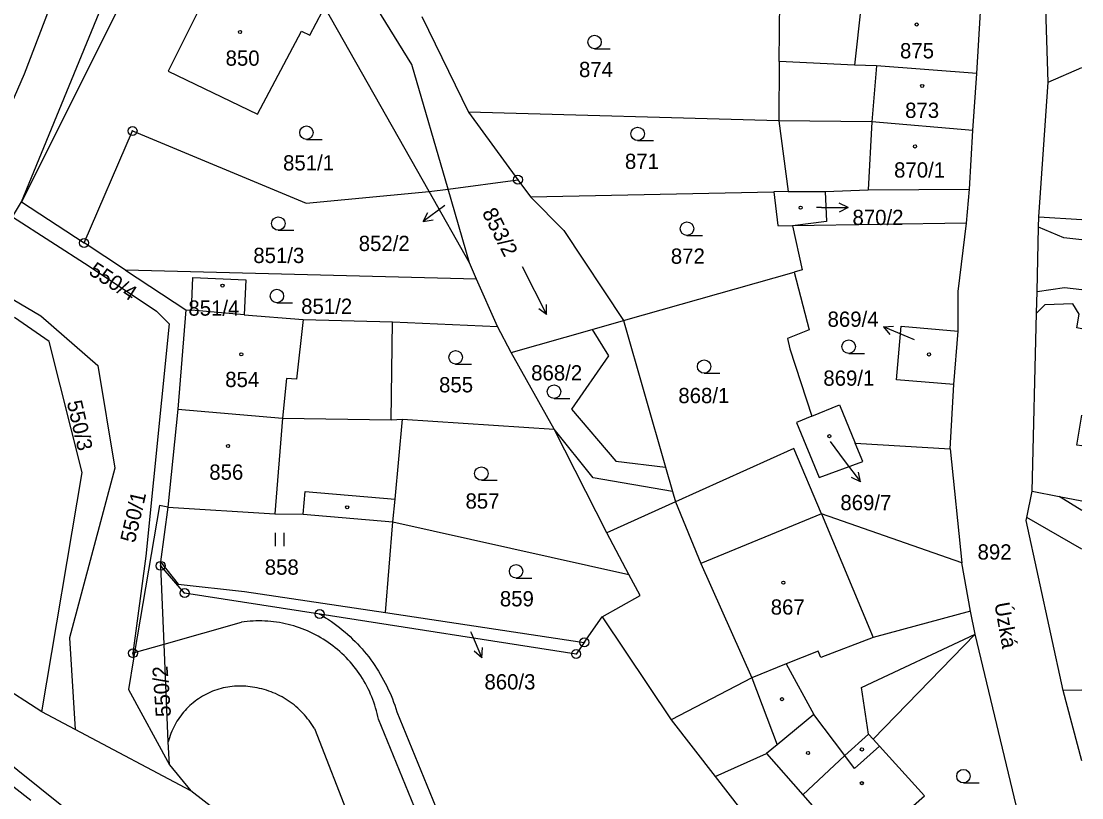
# Model space of a CAD drawing. Extents: x -776606 to -776076, y -974328 to -973875.
# Drawn here: x -776193.8 to -776075.5, y -974133.7 to -974047.1 of the extents above; entities that cross this region are included whole.
import ezdxf

# ---------------------------------------------------------------- set-up
doc = ezdxf.new("R2010")
doc.units = 0
for name, color, linetype in [('Hranice parcel', 7, 'Continuous'), ('Parcelní čísla', 7, 'Continuous'), ('Pop  PČ popisy', 7, 'Continuous'), ('Poz předměty', 7, 'Continuous'), ('Vnitřní kresba', 7, 'Continuous'), ('Značky bodu BP', 7, 'Continuous'), ('Značky budov', 7, 'Continuous'), ('Značky kultur', 7, 'Continuous')]:
    doc.layers.add(name, color=color, linetype=linetype)

msp = doc.modelspace()

# ---------------------------------------------------------------- linework, layer by layer
at = {"layer": 'Hranice parcel'}
for p, q in [((-776172.13, -974024.06), (-776193.76, -974067.27)), ((-776148.31, -974066.12), (-776172.13, -974024.06)), ((-776109.25, -974051.62), (-776109.18, -974044.78)), ((-776087.23, -974052.97), (-776086.8, -974046.07)), ((-776149.12, -974046.61), (-776143.9, -974057.28)), ((-776109.25, -974051.62), (-776109.32, -974058.22)), ((-776079.28, -974053.91), (-776075.52, -974052.27)), ((-776087.67, -974059.31), (-776087.23, -974052.97)), ((-776080.3, -974068.92), (-776079.28, -974053.91)), ((-776109.32, -974058.22), (-776143.9, -974057.28)), ((-776143.9, -974057.28), (-776138.41, -974064.8)), ((-776109.32, -974058.22), (-776108.28, -974066.12)), ((-776146.2, -974065.84), (-776138.41, -974064.8)), ((-776138.41, -974064.8), (-776137.02, -974066.7)), ((-776148.31, -974066.12), (-776146.2, -974065.84)), ((-776143.81, -974074.06), (-776148.31, -974066.12)), ((-776143.81, -974074.06), (-776146.2, -974065.84)), ((-776137.02, -974066.7), (-776109.88, -974066.15)), ((-776108.28, -974066.12), (-776109.88, -974066.15)), ((-776194.77, -974068.92), (-776193.76, -974067.27)), ((-776193.76, -974067.27), (-776186.79, -974071.85)), ((-776194.77, -974068.92), (-776186.22, -974074.45)), ((-776080.33, -974070.1), (-776080.3, -974068.92)), ((-776080.3, -974068.92), (-776075.52, -974069.23)), ((-776088.36, -974069.64), (-776107.78, -974069.96)), ((-776107.78, -974069.96), (-776106.71, -974074.86)), ((-776182.18, -974074.88), (-776186.79, -974071.85)), ((-776143.01, -974075.9), (-776182.18, -974074.88)), ((-776182.18, -974074.88), (-776175.43, -974079.31)), ((-776143.01, -974075.9), (-776143.81, -974074.06)), ((-776106.71, -974074.86), (-776107.61, -974075.12)), ((-776140.7, -974081.18), (-776143.01, -974075.9)), ((-776126.62, -974080.51), (-776107.61, -974075.12)), ((-776175.43, -974079.31), (-776176.35, -974090.4)), ((-776175.43, -974079.31), (-776174.82, -974079.36)), ((-776168.93, -974079.85), (-776174.82, -974079.36)), ((-776168.93, -974079.85), (-776162.35, -974080.4)), ((-776162.35, -974080.4), (-776152.38, -974080.66)), ((-776152.53, -974091.56), (-776152.38, -974080.66)), ((-776152.38, -974080.66), (-776140.7, -974081.18)), ((-776130.11, -974081.5), (-776126.62, -974080.51)), ((-776081.05, -974099.52), (-776080.56, -974079.68)), ((-776139.16, -974084.07), (-776140.7, -974081.18)), ((-776139.16, -974084.07), (-776130.11, -974081.5)), ((-776089.79, -974087.64), (-776089.3, -974081.68)), ((-776134.36, -974092.61), (-776139.16, -974084.07)), ((-776090.2, -974094.79), (-776089.79, -974087.64)), ((-776176.35, -974090.4), (-776177.45, -974101.31)), ((-776152.53, -974091.56), (-776151.27, -974091.49)), ((-776151.27, -974091.49), (-776134.36, -974092.61)), ((-776128.48, -974104.18), (-776134.36, -974092.61)), ((-776100.78, -974094.18), (-776090.2, -974094.79)), ((-776090.2, -974094.79), (-776088.89, -974107.52)), ((-776081.66, -974102.46), (-776081.05, -974099.52)), ((-776081.05, -974099.52), (-776078.04, -974100.11)), ((-776078.04, -974100.11), (-776075.52, -974100.6)), ((-776177.45, -974101.31), (-776178.27, -974107.4)), ((-776153.17, -974113.06), (-776152.34, -974102.95)), ((-776152.34, -974102.95), (-776126.03, -974108.8)), ((-776126.03, -974108.8), (-776128.48, -974104.18)), ((-776178.25, -974107.85), (-776178.27, -974107.4)), ((-776177.87, -974116.6), (-776178.25, -974107.85)), ((-776087.93, -974112.92), (-776088.89, -974107.52)), ((-776191.49, -974124.12), (-776209.73, -974112.42)), ((-776153.17, -974113.06), (-776131, -974116.38)), ((-776131, -974116.38), (-776129, -974113.52)), ((-776129, -974113.52), (-776121.33, -974125.02)), ((-776087.39, -974115.46), (-776087.93, -974112.92)), ((-776098.8, -974127.16), (-776087.39, -974115.46)), ((-776079.84, -974147.11), (-776087.39, -974115.46)), ((-776181.28, -974118.22), (-776181.85, -974121.62)), ((-776181.85, -974121.62), (-776177.26, -974130.04)), ((-776075.52, -974121.72), (-776077.59, -974121.76)), ((-776075.52, -974129.58), (-776077.59, -974121.76)), ((-776192.75, -974134.02), (-776207.36, -974122.58)), ((-776187.78, -974126.09), (-776191.49, -974124.12)), ((-776174.9, -974132.93), (-776187.78, -974126.09)), ((-776098.09, -974127.94), (-776098.8, -974127.16)), ((-776177.26, -974130.04), (-776174.9, -974132.93)), ((-776151.23, -974151.21), (-776174.9, -974132.93))]:
    msp.add_line(p, q, dxfattribs=at)
for points in [[(-776193.76, -974067.27), (-776174.47, -974020.28), (-776171.99, -974017.55)], [(-776146.2, -974065.84), (-776150.23, -974051.95), (-776169.88, -974020.23)], [(-776079.28, -974053.91), (-776079.58, -974044.52), (-776077.53, -974039.59), (-776075.52, -974034.53)], [(-776171.44, -974040.68), (-776177.4, -974052.7), (-776167.44, -974057.5), (-776162.53, -974048.25), (-776161.63, -974048.7), (-776160.2, -974046), (-776171.44, -974040.68)], [(-776087.23, -974052.97), (-776098.4, -974052.1), (-776100.85, -974052.03), (-776109.25, -974051.62)], [(-776087.67, -974059.31), (-776098.95, -974058.35), (-776109.32, -974058.22)], [(-776186.79, -974071.85), (-776181.39, -974059.36), (-776162.03, -974067.4), (-776148.31, -974066.12)], [(-776088.36, -974069.64), (-776088.04, -974065.84), (-776087.67, -974059.31)], [(-776109.88, -974066.15), (-776109.43, -974069.89), (-776107.78, -974069.96)], [(-776108.28, -974066.12), (-776104.12, -974066.1), (-776103.99, -974069.47), (-776107.78, -974069.96)], [(-776137.02, -974066.7), (-776133.27, -974070.47), (-776126.62, -974080.51)], [(-776089.3, -974081.68), (-776089.29, -974077.28), (-776088.36, -974069.64)], [(-776080.56, -974079.68), (-776080.51, -974077.28), (-776080.33, -974070.1)], [(-776075.52, -974071.52), (-776077.51, -974071.29), (-776080.33, -974070.1)], [(-776186.22, -974074.45), (-776178.73, -974079.45), (-776177.29, -974080.87), (-776179.9, -974106.76)], [(-776198.63, -974075.84), (-776191.6, -974079.99), (-776185.25, -974085.51), (-776183.37, -974096.97), (-776188.41, -974115.88), (-776187.78, -974126.09)], [(-776174.82, -974079.36), (-776174.65, -974075.7), (-776168.76, -974075.98), (-776168.93, -974079.85)], [(-776107.61, -974075.12), (-776105.93, -974081.53), (-776108.34, -974082.51), (-776108.07, -974083.66), (-776105.61, -974091.16)], [(-776075.52, -974081.42), (-776076.06, -974081.32), (-776075.81, -974079.8), (-776076.53, -974078.63), (-776079.63, -974078.74), (-776080.56, -974079.68)], [(-776191.49, -974124.12), (-776186.99, -974097.43), (-776190.67, -974082.84), (-776194.55, -974080.16)], [(-776130.11, -974081.5), (-776128.3, -974084.44), (-776132.44, -974090.38), (-776127.47, -974096.19), (-776121.94, -974096.86), (-776121.17, -974099.55), (-776130.03, -974098.04), (-776134.36, -974092.61)], [(-776089.79, -974087.64), (-776096.17, -974087.11), (-776095.67, -974081.13), (-776089.3, -974081.68)], [(-776105.61, -974091.16), (-776102.55, -974089.9), (-776100.78, -974094.18)], [(-776176.35, -974090.4), (-776164.65, -974091.4), (-776152.53, -974091.56)], [(-776152.34, -974102.95), (-776152.11, -974100.42), (-776151.27, -974091.49)], [(-776105.61, -974091.16), (-776107.32, -974091.87), (-776104.79, -974098.01), (-776099.94, -974096.23), (-776100.78, -974094.18)], [(-776075.52, -974094.47), (-776076.05, -974094.38), (-776075.52, -974091.06)], [(-776088.89, -974107.52), (-776104.54, -974102.04), (-776107.63, -974094.75), (-776120.83, -974100.72), (-776128.48, -974104.18)], [(-776075.52, -974101.67), (-776078.04, -974100.11)], [(-776177.45, -974101.31), (-776178.37, -974101.14), (-776181.16, -974117.53), (-776181.28, -974118.22)], [(-776177.45, -974101.31), (-776165.5, -974102.05), (-776162.34, -974102.1), (-776152.34, -974102.95)], [(-776077.59, -974121.76), (-776081.73, -974102.8), (-776081.66, -974102.46)], [(-776075.52, -974105.99), (-776081.66, -974102.46)], [(-776179.9, -974106.76), (-776181.35, -974117.59), (-776181.28, -974118.22)], [(-776178.27, -974107.4), (-776176.29, -974109.9), (-776168.89, -974110.71), (-776153.17, -974113.06)], [(-776131, -974116.38), (-776131.91, -974117.68), (-776160.51, -974113.23), (-776175.58, -974110.89), (-776178.25, -974107.85)], [(-776129, -974113.52), (-776124.77, -974111.17), (-776126.03, -974108.8)], [(-776087.93, -974112.92), (-776098.8, -974115.84), (-776104.62, -974118.06), (-776104.9, -974117.36), (-776108.49, -974118.79), (-776112.33, -974120.32), (-776121.33, -974125.02)], [(-776177.26, -974130.04), (-776177.4, -974127.49), (-776177.87, -974116.6)], [(-776121.33, -974125.02), (-776116.42, -974131.34), (-776106, -974144.74)], [(-776098.85, -974138.57), (-776093.06, -974133.49), (-776098.09, -974127.94)]]:
    msp.add_lwpolyline(points, dxfattribs=at)
at = {"layer": 'Pop  PČ popisy'}
for p, q in [((-776146.54, -974067.68), (-776148.97, -974069.44)), ((-776101.56, -974067.9), (-776102.56, -974067.4)), ((-776148.97, -974069.44), (-776148.45, -974068.45)), ((-776104.56, -974067.9), (-776105.12, -974067.9)), ((-776104.56, -974067.9), (-776101.56, -974067.9)), ((-776101.56, -974067.9), (-776102.56, -974068.4)), ((-776148.97, -974069.44), (-776147.86, -974069.26)), ((-776097.64, -974081.2), (-776096.53, -974081.13)), ((-776094.88, -974082.37), (-776097.64, -974081.2)), ((-776097.64, -974081.2), (-776096.92, -974082.05)), ((-776094.19, -974082.66), (-776094.88, -974082.37)), ((-776103.57, -974094), (-776102.01, -974096.09)), ((-776102.01, -974096.09), (-776100.2, -974098.49)), ((-776100.2, -974098.49), (-776100.41, -974097.39)), ((-776100.2, -974098.49), (-776101.21, -974097.99)), ((-776143.68, -974115.16), (-776143.61, -974115.33)), ((-776143.61, -974115.33), (-776142.44, -974118.09)), ((-776142.44, -974118.09), (-776143.29, -974117.37)), ((-776142.44, -974118.09), (-776142.37, -974116.97))]:
    msp.add_line(p, q, dxfattribs=at)
at = {"layer": 'Poz předměty'}
for p, q in [((-776188.57, -974040.14), (-776193.46, -974053.03)), ((-776193.46, -974053.03), (-776205.51, -974080.41))]:
    msp.add_line(p, q, dxfattribs=at)
at = {"layer": 'Vnitřní kresba'}
for p, q in [((-776100.12, -974045.3), (-776100.85, -974052.03)), ((-776098.4, -974052.1), (-776098.95, -974058.35)), ((-776098.95, -974058.35), (-776099.35, -974065.94)), ((-776104.12, -974066.1), (-776099.35, -974065.94)), ((-776099.35, -974065.94), (-776088.04, -974065.84)), ((-776080.51, -974077.28), (-776077.46, -974076.83)), ((-776077.46, -974076.83), (-776075.52, -974077.04)), ((-776162.35, -974080.4), (-776163.09, -974087.03)), ((-776126.62, -974080.51), (-776121.94, -974096.86)), ((-776164.21, -974086.98), (-776164.65, -974091.4)), ((-776163.09, -974087.03), (-776164.21, -974086.98)), ((-776164.65, -974091.4), (-776165.5, -974102.05)), ((-776162.34, -974102.1), (-776162.12, -974099.58)), ((-776162.12, -974099.58), (-776152.11, -974100.42)), ((-776121.17, -974099.55), (-776120.83, -974100.72)), ((-776120.83, -974100.72), (-776118, -974107.6)), ((-776104.54, -974102.04), (-776118, -974107.6)), ((-776104.54, -974102.04), (-776098.8, -974115.84)), ((-776118, -974107.6), (-776112.33, -974120.32)), ((-776177.87, -974116.6), (-776169.25, -974114.14)), ((-776100.08, -974121.41), (-776087.39, -974115.46)), ((-776181.16, -974117.53), (-776177.87, -974116.6)), ((-776181.16, -974117.53), (-776181.35, -974117.59)), ((-776108.49, -974118.79), (-776105.41, -974124.43)), ((-776112.33, -974120.32), (-776109.49, -974127.79)), ((-776099.3, -974126.61), (-776100.08, -974121.41)), ((-776201.86, -974124.47), (-776164.7, -974154.27)), ((-776151.91, -974124.13), (-776143.06, -974145.68)), ((-776105.41, -974124.43), (-776109.49, -974127.79)), ((-776101.95, -974129.01), (-776105.41, -974124.43)), ((-776145.11, -974146.49), (-776153.97, -974124.96)), ((-776161.1, -974126), (-776151.23, -974151.21)), ((-776101.95, -974129.01), (-776099.3, -974126.61)), ((-776099.3, -974126.61), (-776098.8, -974127.16)), ((-776109.49, -974127.79), (-776110.68, -974128.76)), ((-776098.09, -974127.94), (-776100.86, -974130.45)), ((-776116.42, -974131.34), (-776110.68, -974128.76)), ((-776110.68, -974128.76), (-776106.63, -974133.38)), ((-776101.95, -974129.01), (-776106.63, -974133.38)), ((-776100.86, -974130.45), (-776101.95, -974129.01)), ((-776106.63, -974133.38), (-776100.67, -974140.17))]:
    msp.add_line(p, q, dxfattribs=at)
for points in [[(-776160.51, -974113.23), (-776160.18, -974113.43), (-776159.85, -974113.63), (-776159.53, -974113.84), (-776159.21, -974114.06), (-776158.9, -974114.28), (-776158.59, -974114.51), (-776158.29, -974114.74), (-776157.99, -974114.98), (-776157.69, -974115.23), (-776157.41, -974115.48), (-776157.12, -974115.74), (-776156.84, -974116.01), (-776156.57, -974116.28), (-776156.3, -974116.55), (-776156.04, -974116.83), (-776155.79, -974117.12), (-776155.54, -974117.41), (-776155.29, -974117.71), (-776155.05, -974118.01), (-776154.82, -974118.32), (-776154.59, -974118.63), (-776154.38, -974118.95), (-776154.16, -974119.27), (-776153.96, -974119.59), (-776153.76, -974119.92), (-776153.57, -974120.25), (-776153.38, -974120.59), (-776153.2, -974120.93), (-776153.03, -974121.27), (-776152.86, -974121.62), (-776152.7, -974121.97), (-776152.55, -974122.32), (-776152.41, -974122.68), (-776152.27, -974123.04), (-776152.15, -974123.4), (-776152.02, -974123.76), (-776151.91, -974124.13)], [(-776153.97, -974124.96), (-776154.04, -974124.64), (-776154.11, -974124.32), (-776154.19, -974124), (-776154.28, -974123.69), (-776154.38, -974123.37), (-776154.48, -974123.06), (-776154.59, -974122.75), (-776154.71, -974122.45), (-776154.84, -974122.14), (-776154.97, -974121.84), (-776155.12, -974121.55), (-776155.27, -974121.26), (-776155.42, -974120.97), (-776155.58, -974120.68), (-776155.75, -974120.4), (-776155.93, -974120.12), (-776156.11, -974119.85), (-776156.3, -974119.58), (-776156.5, -974119.32), (-776156.7, -974119.06), (-776156.91, -974118.81), (-776157.12, -974118.56), (-776157.34, -974118.32), (-776157.57, -974118.08), (-776157.8, -974117.85), (-776158.04, -974117.62), (-776158.28, -974117.4), (-776158.53, -974117.18), (-776158.78, -974116.98), (-776159.04, -974116.77), (-776159.3, -974116.58), (-776159.57, -974116.39), (-776159.84, -974116.2), (-776160.12, -974116.03), (-776160.4, -974115.86), (-776160.69, -974115.7), (-776160.97, -974115.54), (-776161.27, -974115.39), (-776161.56, -974115.25), (-776161.86, -974115.11), (-776162.17, -974114.99), (-776162.47, -974114.87), (-776162.78, -974114.76), (-776163.09, -974114.65), (-776163.4, -974114.55), (-776163.72, -974114.46), (-776164.04, -974114.38), (-776164.36, -974114.31), (-776164.68, -974114.24), (-776165, -974114.18), (-776165.33, -974114.13), (-776165.65, -974114.09), (-776165.98, -974114.05), (-776166.3, -974114.03), (-776166.63, -974114.01), (-776166.96, -974114), (-776167.29, -974113.99), (-776167.62, -974114), (-776167.94, -974114.01), (-776168.27, -974114.03), (-776168.6, -974114.06), (-776168.93, -974114.1), (-776169.25, -974114.14)], [(-776168.02, -974121.37), (-776168.27, -974121.33), (-776168.52, -974121.3), (-776168.77, -974121.28), (-776169.02, -974121.26), (-776169.27, -974121.25), (-776169.52, -974121.25), (-776169.77, -974121.26), (-776170.02, -974121.27), (-776170.27, -974121.3), (-776170.52, -974121.33), (-776170.77, -974121.36), (-776171.02, -974121.41), (-776171.27, -974121.46), (-776171.51, -974121.52), (-776171.75, -974121.59), (-776171.99, -974121.67), (-776172.23, -974121.75), (-776172.46, -974121.84), (-776172.7, -974121.93), (-776172.93, -974122.04), (-776173.15, -974122.15), (-776173.37, -974122.27), (-776173.59, -974122.39), (-776173.81, -974122.52), (-776174.02, -974122.66), (-776174.22, -974122.8), (-776174.42, -974122.95), (-776174.62, -974123.11), (-776174.81, -974123.27), (-776175, -974123.44), (-776175.18, -974123.61), (-776175.36, -974123.79), (-776175.53, -974123.97), (-776175.7, -974124.16), (-776175.85, -974124.36), (-776176.01, -974124.56), (-776176.16, -974124.76), (-776176.3, -974124.97), (-776176.43, -974125.18), (-776176.56, -974125.4), (-776176.68, -974125.62), (-776176.8, -974125.84), (-776176.9, -974126.07), (-776177, -974126.3), (-776177.1, -974126.53), (-776177.18, -974126.77), (-776177.26, -974127.01), (-776177.33, -974127.25), (-776177.4, -974127.49)], [(-776161.1, -974126), (-776161.24, -974125.77), (-776161.38, -974125.54), (-776161.54, -974125.32), (-776161.69, -974125.1), (-776161.86, -974124.89), (-776162.03, -974124.68), (-776162.2, -974124.47), (-776162.39, -974124.28), (-776162.57, -974124.08), (-776162.77, -974123.89), (-776162.96, -974123.71), (-776163.17, -974123.53), (-776163.37, -974123.36), (-776163.59, -974123.2), (-776163.8, -974123.04), (-776164.03, -974122.89), (-776164.25, -974122.74), (-776164.48, -974122.6), (-776164.71, -974122.46), (-776164.95, -974122.34), (-776165.19, -974122.22), (-776165.44, -974122.1), (-776165.69, -974122), (-776165.94, -974121.9), (-776166.19, -974121.81), (-776166.45, -974121.72), (-776166.7, -974121.65), (-776166.96, -974121.58), (-776167.22, -974121.51), (-776167.49, -974121.46), (-776167.75, -974121.41), (-776168.02, -974121.37)]]:
    msp.add_lwpolyline(points, dxfattribs=at)
at = {"layer": 'Značky bodu BP'}
for centre, radius in [((-776181.39, -974059.36), 0.5), ((-776181.39, -974059.36), 0.0303), ((-776138.41, -974064.8), 0.5), ((-776138.41, -974064.8), 0.0303), ((-776186.79, -974071.85), 0.5), ((-776186.79, -974071.85), 0.0303), ((-776178.25, -974107.85), 0.5), ((-776178.25, -974107.85), 0.0303), ((-776175.58, -974110.89), 0.5), ((-776175.58, -974110.89), 0.0303), ((-776160.51, -974113.23), 0.5), ((-776160.51, -974113.23), 0.0303), ((-776131, -974116.38), 0.5), ((-776181.35, -974117.59), 0.5), ((-776131.91, -974117.68), 0.5), ((-776131, -974116.38), 0.0303), ((-776181.35, -974117.59), 0.0303), ((-776131.91, -974117.68), 0.0303)]:
    msp.add_circle(centre, radius, dxfattribs=at)
at = {"layer": 'Značky budov'}
for centre in [(-776093.93, -974047.5), (-776169.4, -974048.32), (-776093.32, -974054.35), (-776094.11, -974061.09), (-776106.88, -974067.92), (-776171.35, -974076.61), (-776169.26, -974084.26), (-776092.55, -974084.28), (-776103.67, -974093.39), (-776170.74, -974094.48), (-776157.45, -974101.32), (-776108.8, -974109.73), (-776108.95, -974122.71), (-776100.04, -974128.32), (-776106.05, -974128.72), (-776100.05, -974132.08)]:
    msp.add_circle(centre, 0.175, dxfattribs=at)
at = {"layer": 'Značky kultur'}
for p, q in [((-776129.86, -974050.2), (-776128.11, -974050.2)), ((-776161.99, -974060.3), (-776160.24, -974060.3)), ((-776125.05, -974060.44), (-776123.3, -974060.44)), ((-776165.13, -974070.44), (-776163.38, -974070.44)), ((-776119.55, -974071.01), (-776117.8, -974071.01)), ((-776137.92, -974074.48), (-776135.2, -974079.82)), ((-776165.29, -974078.52), (-776163.54, -974078.52)), ((-776135.2, -974079.82), (-776136.09, -974079.18)), ((-776135.2, -974079.82), (-776135.2, -974078.72)), ((-776101.51, -974084.16), (-776099.76, -974084.16)), ((-776145.35, -974085.35), (-776143.6, -974085.35)), ((-776117.64, -974086.38), (-776115.89, -974086.38)), ((-776134.38, -974089.18), (-776132.63, -974089.18)), ((-776142.48, -974098.31), (-776140.73, -974098.31)), ((-776165.46, -974105.66), (-776165.46, -974104.16)), ((-776164.46, -974105.66), (-776164.46, -974104.16)), ((-776138.61, -974109.21), (-776136.86, -974109.21)), ((-776088.72, -974132.05), (-776086.97, -974132.05))]:
    msp.add_line(p, q, dxfattribs=at)
for centre in [(-776129.86, -974049.45), (-776161.99, -974059.55), (-776125.05, -974059.69), (-776165.13, -974069.69), (-776119.55, -974070.26), (-776165.29, -974077.77), (-776101.51, -974083.41), (-776145.35, -974084.6), (-776117.64, -974085.63), (-776134.38, -974088.43), (-776142.48, -974097.56), (-776138.61, -974108.46), (-776088.72, -974131.3)]:
    msp.add_circle(centre, 0.75, dxfattribs=at)

# ---------------------------------------------------------------- texts
at = {"layer": 'Parcelní čísla'}
for s, p in [('875', (-776095.79, -974051.27)), ('850', (-776171.01, -974052.09)), ('874', (-776131.59, -974053.36)), ('873', (-776095.22, -974057.91)), ('871', (-776126.47, -974063.6)), ('851/1', (-776164.6, -974063.77)), ('870/1', (-776096.45, -974064.56)), ('870/2', (-776101.09, -974069.85)), ('852/2', (-776156.16, -974072.75)), ('851/3', (-776167.92, -974074.09)), ('872', (-776121.35, -974074.17)), ('851/4', (-776175.16, -974079.96)), ('851/2', (-776162.58, -974079.76)), ('869/4', (-776103.87, -974081.2)), ('868/2', (-776136.93, -974087.18)), ('854', (-776171.05, -974087.92)), ('869/1', (-776104.34, -974087.77)), ('855', (-776147.2, -974088.51)), ('868/1', (-776120.51, -974089.71)), ('856', (-776172.83, -974098.25)), ('857', (-776144.25, -974101.47)), ('869/7', (-776102.44, -974101.65)), ('892', (-776087.14, -974107.15)), ('858', (-776166.64, -974108.84)), ('859', (-776140.42, -974112.37)), ('867', (-776110.21, -974113.29)), ('860/3', (-776142.14, -974121.63))]:
    msp.add_text(s, height=1.7, dxfattribs=at).set_placement(p)
for s, rotation, p in [('853/2', 297, (-776142.45, -974068.47)), ('550/4', 327, (-776186.39, -974075.29)), ('550/3', 283, (-776188.73, -974089.6)), ('550/1', 77, (-776181.13, -974105.36)), ('550/2', 94, (-776177.09, -974124.64))]:
    msp.add_text(s, height=1.7, rotation=rotation, dxfattribs=at).set_placement(p)
at = {"layer": 'Pop  PČ popisy'}
msp.add_text('Úzká', height=1.7, rotation=280, dxfattribs=at).set_placement((-776085.27, -974112.06))

doc.saveas('drawing.dxf')
